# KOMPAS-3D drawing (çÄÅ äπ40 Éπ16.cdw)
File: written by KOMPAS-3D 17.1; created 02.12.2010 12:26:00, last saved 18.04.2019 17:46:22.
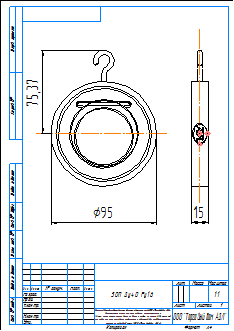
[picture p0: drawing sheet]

Sheet 1: A4, portrait

Title block, sheet 1: name: ЗОП Ду40 Ру16; material: Внимание! Данный продукт является объектом авторского права ООО «Торговый Дом АДЛ». / Запрещается изменение, копирование, распространение / (в том числе путем копирования на другие сайты и ресурсы в Интернете) / или любое иное использование информации и объектов без предварительного / согласия правообладателя (ООО «Торговый Дом АДЛ»).; scale: 1:1; sheets: 1; organisation: ООО "Торговый дом АДЛ"; sheet format: A4; stored path: \\adlc.lan\data\АДЛ_ПКД\3D-модели\ADL production\Клапаны обратные ГРАНЛОК\ЗОП\KOMPAS 2D\ЗОП Ду40 Ру16.cdw

Views: Спереди 1, Проекционный вид 2
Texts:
  bsv
  adl
Dimensions and other numbers on the sheet: 95; 15; 75,37; 1:1; 1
